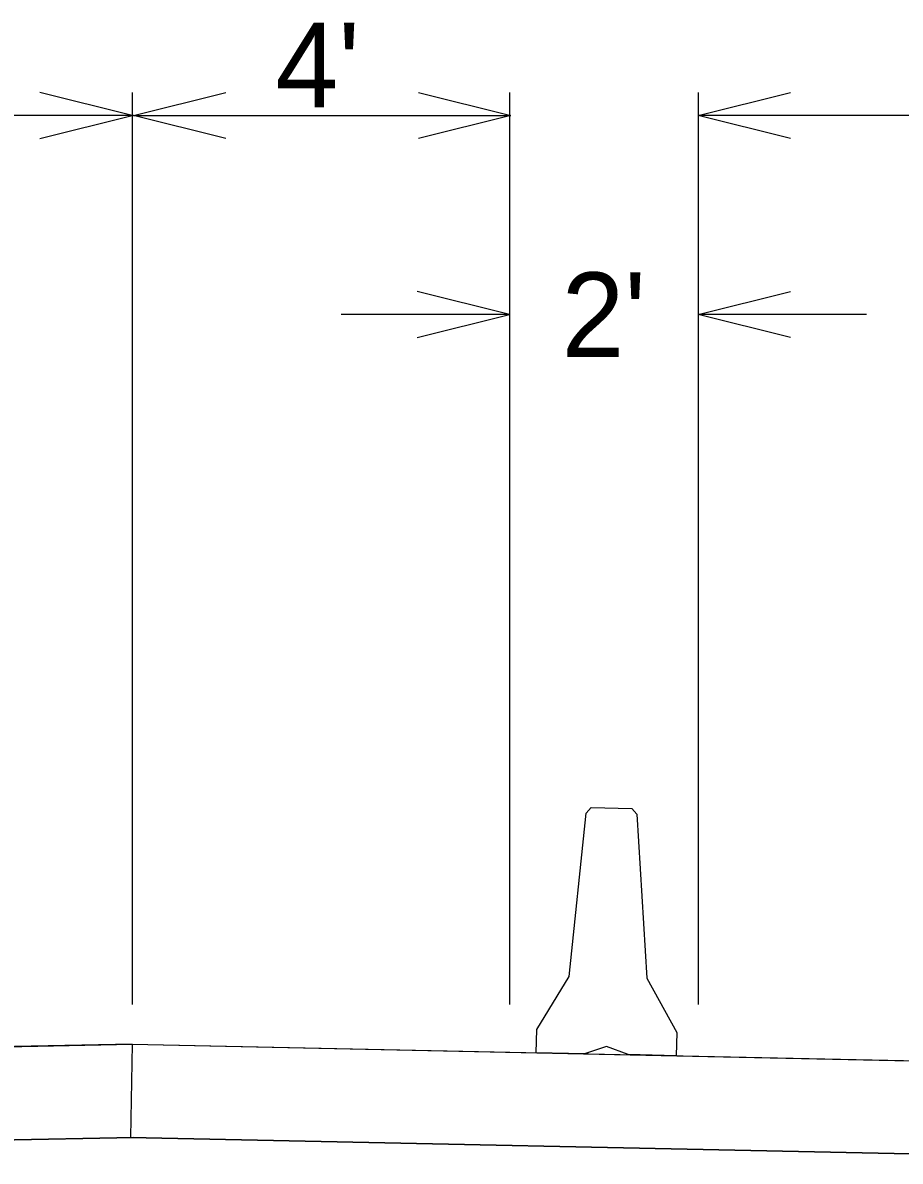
# Model space of a CAD drawing. Extents: x 10133 to 81668, y 4856 to 11018.
# Drawn here: x 11680.6 to 11836.4, y 8722.5 to 8924.5 of the extents above; entities that cross this region are included whole.
import ezdxf

# ---------------------------------------------------------------- set-up
doc = ezdxf.new("R2010")
doc.units = 0
for name, color, linetype in [('dsnXsPCCPavement', 7, 'Continuous'), ('dsnXsPCCPavementBottom', 7, 'Continuous'), ('dsnXsShldrEarthFill', 7, 'Continuous'), ('dsnXsShldrGranular', 7, 'Continuous'), ('dsnXsShldrGranularBottom', 7, 'Continuous')]:
    doc.layers.add(name, color=color, linetype=linetype)

msp = doc.modelspace()

# ---------------------------------------------------------------- linework, layer by layer
at = {"layer": 'dsnXsPCCPavement'}
msp.add_lwpolyline([(11771.86, 8745.82), (11777.58, 8755.26), (11780.6, 8784.23), (11781.53, 8785.23), (11788.7, 8785.08), (11789.59, 8784.04), (11791.38, 8754.97), (11796.69, 8745.29), (11796.6, 8741.2), (11788.05, 8741.38), (11784.22, 8742.82), (11780.33, 8741.54), (11771.77, 8741.72)], close=True, dxfattribs=at)
at = {"layer": 'dsnXsPCCPavementBottom'}
for p, q in [((11700, 8912.17), (11700, 8750.3)), ((11767, 8912.17), (11767, 8750.3)), ((11800.5, 8912.17), (11800.5, 8750.3)), ((11700.24, 8908.07), (11501.57, 8908.07)), ((11700.24, 8908.07), (11767.24, 8908.07)), ((11898.67, 8908.07), (11800.5, 8908.07)), ((11767, 8872.75), (11737.1, 8872.75)), ((11830.4, 8872.75), (11800.5, 8872.75))]:
    msp.add_line(p, q, dxfattribs=at)
for points in [[(11683.61, 8903.97), (11700, 8908.07), (11683.61, 8912.17)], [(11716.63, 8903.97), (11700.24, 8908.07), (11716.63, 8912.17)], [(11750.85, 8912.17), (11767.24, 8908.07), (11750.85, 8903.97)], [(11816.89, 8903.97), (11800.5, 8908.07), (11816.89, 8912.17)], [(11750.61, 8868.65), (11767, 8872.75), (11750.61, 8876.84)], [(11816.89, 8868.65), (11800.5, 8872.75), (11816.89, 8876.84)]]:
    msp.add_lwpolyline(points, dxfattribs=at)
at = {"layer": 'dsnXsShldrGranular'}
for p, q in [((11700.35, 8726.7), (11501.33, 8722.47)), ((11898.67, 8722.47), (11699.65, 8726.7))]:
    msp.add_line(p, q, dxfattribs=at)
for points in [[(11501.33, 8722.47), (11501.57, 8739.03), (11700, 8743.25)], [(11700, 8743.25), (11898.43, 8739.03), (11898.67, 8722.47)]]:
    msp.add_lwpolyline(points, dxfattribs=at)
at = {"layer": 'dsnXsShldrGranularBottom'}
for p, q in [((11700, 8743.25), (11501.57, 8739.03)), ((11700, 8743.25), (11699.76, 8726.68)), ((11700, 8743.25), (11898.43, 8739.03)), ((11501.33, 8722.47), (11700.35, 8726.7)), ((11699.65, 8726.7), (11898.67, 8722.47))]:
    msp.add_line(p, q, dxfattribs=at)

# ---------------------------------------------------------------- texts
at = {"layer": 'dsnXsShldrEarthFill'}
for s, p in [("4'", (11725.47, 8909.53)), ("2'", (11776.25, 8865.22))]:
    msp.add_text(s, height=15, dxfattribs=at).set_placement(p)

doc.saveas('drawing.dxf')
